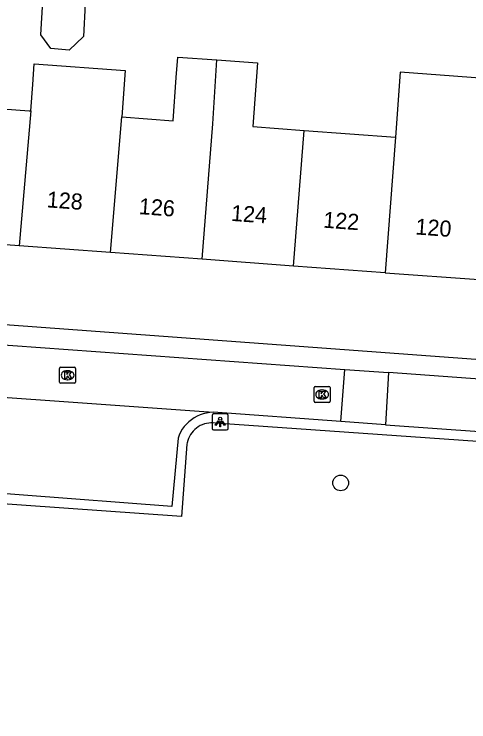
# Model space of a CAD drawing. Extents: x 160304 to 160954, y 383686 to 384161.
# Drawn here: x 160524.56 to 160552.85, y 383895.48 to 383939.55 of the extents above; entities that cross this region are included whole.
import ezdxf

# ---------------------------------------------------------------- set-up
doc = ezdxf.new("R2010")
doc.units = 0
for name, color, linetype in [('IMGEO_Boom', 7, 'Continuous'), ('IMGEO_Kolk', 7, 'Continuous'), ('IMGEO_Lichtpunt', 7, 'Continuous'), ('IMGEO_Pand', 7, 'Continuous'), ('IMGEO_Pand_nummerreeks', 7, 'Continuous'), ('IMGEO_Rijbaan_lokaal_open', 7, 'Continuous'), ('IMGEO_Voetpad_open', 7, 'Continuous')]:
    doc.layers.add(name, color=color, linetype=linetype)

msp = doc.modelspace()

# ---------------------------------------------------------------- linework, layer by layer
at = {"layer": 'IMGEO_Boom'}
msp.add_circle((160544.875, 383910.356), 0.489, dxfattribs=at)
at = {"layer": 'IMGEO_Kolk'}
for p, q in [((160527.385, 383916.64), (160527.385, 383917.492)), ((160527.46, 383917.566), (160528.312, 383917.566)), ((160527.873, 383917.346), (160527.898, 383917.346)), ((160528.386, 383917.492), (160528.386, 383916.64)), ((160527.896, 383916.786), (160527.871, 383916.786)), ((160528.312, 383916.566), (160527.46, 383916.566)), ((160543.221, 383915.44), (160543.221, 383916.292)), ((160543.296, 383916.366), (160544.148, 383916.366)), ((160544.222, 383916.292), (160544.222, 383915.44)), ((160543.709, 383916.146), (160543.734, 383916.146)), ((160543.732, 383915.586), (160543.707, 383915.586)), ((160544.148, 383915.366), (160543.296, 383915.366))]:
    msp.add_line(p, q, dxfattribs=at)
for points in [[(160527.385, 383916.64), (160527.385, 383917.492)], [(160527.46, 383917.566), (160528.312, 383917.566)], [(160527.706, 383917.266), (160527.829, 383917.266), (160527.829, 383917.115), (160527.959, 383917.266), (160528.123, 383917.266), (160527.977, 383917.115), (160528.13, 383916.866), (160527.978, 383916.866), (160527.893, 383917.03), (160527.829, 383916.963), (160527.829, 383916.866), (160527.706, 383916.866), (160527.706, 383917.266)], [(160528.386, 383917.492), (160528.386, 383916.64)], [(160528.312, 383916.566), (160527.46, 383916.566)], [(160543.221, 383915.44), (160543.221, 383916.292)], [(160543.296, 383916.366), (160544.148, 383916.366)], [(160544.222, 383916.292), (160544.222, 383915.44)], [(160543.542, 383916.066), (160543.665, 383916.066), (160543.665, 383915.915), (160543.795, 383916.066), (160543.959, 383916.066), (160543.813, 383915.915), (160543.966, 383915.666), (160543.814, 383915.666), (160543.729, 383915.83), (160543.665, 383915.763), (160543.665, 383915.666), (160543.542, 383915.666), (160543.542, 383916.066)], [(160544.148, 383915.366), (160543.296, 383915.366)]]:
    msp.add_lwpolyline(points, dxfattribs=at)
for centre, start, end in [((160527.462, 383917.49), 91.552, 178.448), ((160527.462, 383917.49), 91.552, 178.448), ((160528.31, 383917.49), 1.552, 88.448), ((160528.31, 383917.49), 1.552, 88.448), ((160527.462, 383916.642), 181.552, 268.448), ((160527.462, 383916.642), 181.552, 268.448), ((160528.31, 383916.642), 271.552, 358.448), ((160528.31, 383916.642), 271.552, 358.448), ((160543.298, 383916.29), 91.552, 178.448), ((160543.298, 383916.29), 91.552, 178.448), ((160544.146, 383916.29), 1.552, 88.448), ((160544.146, 383916.29), 1.552, 88.448), ((160543.298, 383915.442), 181.552, 268.448), ((160543.298, 383915.442), 181.552, 268.448), ((160544.146, 383915.442), 271.552, 358.448), ((160544.146, 383915.442), 271.552, 358.448)]:
    msp.add_arc(centre, 0.0765, start, end, dxfattribs=at)
for centre, major_axis, ratio, start_param, end_param in [((160527.872, 383917.066), (-0.387, 0.002), 0.722429, 4.712389, 7.853982), ((160527.897, 383917.066), (-0.39, 0.002), 0.717154, 1.570796, 4.712389), ((160543.708, 383915.866), (-0.387, 0.002), 0.722429, 4.712389, 7.853982), ((160543.733, 383915.866), (-0.39, 0.002), 0.717154, 1.570796, 4.712389)]:
    msp.add_ellipse(centre, major_axis=major_axis, ratio=ratio, start_param=start_param, end_param=end_param, dxfattribs=at)
at = {"layer": 'IMGEO_Lichtpunt'}
for p, q in [((160536.879, 383914.561), (160536.879, 383913.754)), ((160536.879, 383914.561), (160536.879, 383913.754)), ((160537.781, 383914.656), (160536.973, 383914.656)), ((160537.781, 383914.656), (160536.973, 383914.656)), ((160537.875, 383913.754), (160537.875, 383914.561)), ((160537.875, 383913.754), (160537.875, 383914.561)), ((160536.973, 383913.66), (160537.781, 383913.66)), ((160536.973, 383913.66), (160537.781, 383913.66))]:
    msp.add_line(p, q, dxfattribs=at)
for points in [[(160537.253, 383914.225), (160537.292, 383914.197), (160537.104, 383913.935), (160537.066, 383913.962), (160537.253, 383914.225)], [(160537.355, 383914.177), (160537.402, 383914.177), (160537.402, 383913.855), (160537.355, 383913.855), (160537.355, 383914.177)], [(160537.465, 383914.197), (160537.503, 383914.224), (160537.69, 383913.962), (160537.651, 383913.934), (160537.465, 383914.197)]]:
    msp.add_lwpolyline(points, dxfattribs=at)
msp.add_circle((160537.378, 383914.359), 0.0994, dxfattribs=at)
for centre, start, end in [((160536.973, 383914.561), 90, 180), ((160536.973, 383914.561), 90, 180), ((160537.781, 383914.561), 0, 90), ((160537.781, 383914.561), 0, 90), ((160536.973, 383913.754), 180, 270), ((160536.973, 383913.754), 180, 270), ((160537.781, 383913.754), 270, 0), ((160537.781, 383913.754), 270, 360)]:
    msp.add_arc(centre, 0.0946, start, end, dxfattribs=at)
at = {"layer": 'IMGEO_Pand'}
for points in [[(160526.843, 383937.412), (160526.217, 383938.266), (160526.341, 383940.366), (160527.131, 383941.126), (160528.363, 383941.01), (160528.986, 383940.194), (160528.866, 383938.162), (160527.975, 383937.306), (160526.843, 383937.412)], [(160531.251, 383933.15), (160534.447, 383932.915), (160534.645, 383935.61), (160534.739, 383936.882), (160537.167, 383936.703)], [(160536.26, 383924.285), (160536.93, 383932.73), (160537.167, 383936.703)], [(160537.167, 383936.703), (160539.701, 383936.517), (160539.409, 383932.55), (160542.6, 383932.315)], [(160525.589, 383933.526), (160525.719, 383935.166), (160525.815, 383936.464), (160531.459, 383936.048), (160531.251, 383933.15)], [(160554.076, 383935.092), (160554.094, 383935.53), (160551.058, 383935.753), (160548.576, 383935.935), (160548.279, 383931.897)], [(160519.677, 383933.96), (160522.164, 383933.777), (160525.488, 383933.533), (160525.589, 383933.526)], [(160525.589, 383933.526), (160524.883, 383925.122)], [(160530.561, 383924.705), (160531.251, 383933.15)], [(160541.942, 383923.867), (160542.6, 383932.315)], [(160542.6, 383932.315), (160548.279, 383931.897)], [(160548.279, 383931.897), (160547.64, 383923.448)], [(160547.64, 383923.448), (160553.467, 383923.019), (160553.736, 383926.669)], [(160524.883, 383925.122), (160519.059, 383925.551)], [(160530.561, 383924.705), (160524.883, 383925.122)], [(160536.26, 383924.285), (160530.561, 383924.705)], [(160541.942, 383923.867), (160536.26, 383924.285)], [(160547.64, 383923.448), (160541.942, 383923.867)]]:
    msp.add_lwpolyline(points, dxfattribs=at)
at = {"layer": 'IMGEO_Rijbaan_lokaal_open'}
for points in [[(160514.136, 383919.672), (160545.126, 383917.424)], [(160544.892, 383914.18), (160545.126, 383917.424)], [(160545.126, 383917.424), (160547.853, 383917.226)], [(160547.853, 383917.226), (160547.655, 383913.98)], [(160587.654, 383882.722), (160587.315, 383883.141), (160574.877, 383906.644), (160573.929, 383908.129), (160572.852, 383909.524), (160571.655, 383910.817), (160570.347, 383911.997), (160568.939, 383913.056), (160567.441, 383913.986), (160565.867, 383914.777), (160564.229, 383915.425), (160562.539, 383915.924), (160560.811, 383916.27), (160560.601, 383916.301), (160547.853, 383917.226)], [(160514.553, 383916.371), (160536.933, 383914.754)], [(160544.892, 383914.18), (160536.933, 383914.754)], [(160547.655, 383913.98), (160544.892, 383914.18)], [(160547.655, 383913.98), (160553.8, 383913.536)]]:
    msp.add_lwpolyline(points, dxfattribs=at)
at = {"layer": 'IMGEO_Voetpad_open'}
for points in [[(160518.927, 383923.923), (160518.814, 383922.53), (160519.759, 383920.534), (160564.54, 383917.241), (160564.726, 383919.653), (160572.939, 383919.144), (160577.354, 383910.75), (160574.721, 383909.349), (160588.559, 383883.201)], [(160536.933, 383914.754), (160536.727, 383914.742), (160536.522, 383914.712), (160536.321, 383914.663), (160536.126, 383914.597), (160535.937, 383914.513), (160535.756, 383914.413), (160535.585, 383914.297), (160535.425, 383914.166), (160535.277, 383914.022), (160535.142, 383913.865), (160535.023, 383913.697), (160534.919, 383913.518), (160534.831, 383913.331), (160534.76, 383913.137), (160534.37, 383908.892), (160515.887, 383910.291)], [(160553.378, 383912.947), (160537.081, 383914.077), (160536.943, 383914.092), (160536.804, 383914.095), (160536.666, 383914.085), (160536.529, 383914.063), (160536.395, 383914.029), (160536.264, 383913.982), (160536.138, 383913.925), (160536.017, 383913.856), (160535.903, 383913.777), (160535.797, 383913.688), (160535.699, 383913.59), (160535.61, 383913.483), (160535.531, 383913.369), (160535.463, 383913.249), (160535.405, 383913.123), (160535.359, 383912.992), (160535.325, 383912.857), (160535.311, 383912.777), (160534.978, 383908.258), (160515.342, 383909.655)]]:
    msp.add_lwpolyline(points, dxfattribs=at)

# ---------------------------------------------------------------- texts
at = {"layer": 'IMGEO_Pand_nummerreeks'}
for s, rotation, p in [('128', 355.7888, (160526.567, 383927.525)), ('126', 355.7913, (160532.297, 383927.104)), ('124', 355.7913, (160538.032, 383926.682)), ('122', 355.7913, (160543.765, 383926.26)), ('120', 355.7888, (160549.505, 383925.837))]:
    msp.add_text(s, height=1, rotation=rotation, dxfattribs=at).set_placement(p)

doc.saveas('drawing.dxf')
